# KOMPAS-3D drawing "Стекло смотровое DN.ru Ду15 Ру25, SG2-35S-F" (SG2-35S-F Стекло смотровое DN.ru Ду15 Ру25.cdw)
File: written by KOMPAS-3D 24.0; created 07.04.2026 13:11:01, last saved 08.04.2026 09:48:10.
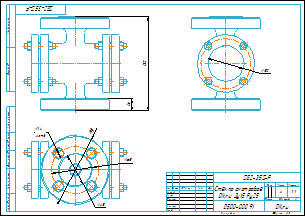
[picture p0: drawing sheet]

Document properties: Автор: Main; Форматы листов документа: A3; Полное имя файла: SG2-35S-F Стекло смотровое DN.ru Ду15 Ру25.m3d; Масса: 4; Наименование: Стекло смотровое DN.ru Ду15 Ру25; Количество листов документа: 1; Примечание: D500-00091

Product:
- Body: Тело 1  | qty 1
    Масса: 3.175709
- Part/product: Стекло смотровое DN.ru Ду15 Ру25  | designation SG2-35S-F
    Масса: 4
    Раздел спецификации: Прочие изделия
    Примечание: D500-00091

Views: Вид 1, Снизу, Проекционный вид 3
Referenced files in D:\DN.ru Аутсерс\Стекло смотровое DN.ru\Стекло смотровое DN.ru SG2-34G-F тип В ГОСТ 21836-2021 Ду100 Ру16, углеродистая сталь, фланцевое\: SG2-34G-F тип В Стекло смотровое DN.ru Ду100 Ру16.m3d, SG2-34G-F тип ВСтекло смотровое DN.ru Ду100 Ру16.cdw
Referenced files in D:\DN.ru Аутсерс\Стекло смотровое DN.ru\SG2-35S-F Стекло смотровое DN.ru Ду15 Ру25\: SG2-35S-F Стекло смотровое DN.ru Ду15 Ру25.m3d
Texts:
  SG2-35S-F
  Стекло смотровое
  DN.ru Ду15 Ру25
  Стекло смотровое DN.ru Ду15 Ру25
  SG2-35S-F Стекло смотровое DN.ru Ду15 Ру25
Dimensions and other numbers on the sheet: 0; 3; 2; 4; 130; 16; 50; 1:1; 1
